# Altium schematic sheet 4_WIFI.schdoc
size 302 x 215 mm
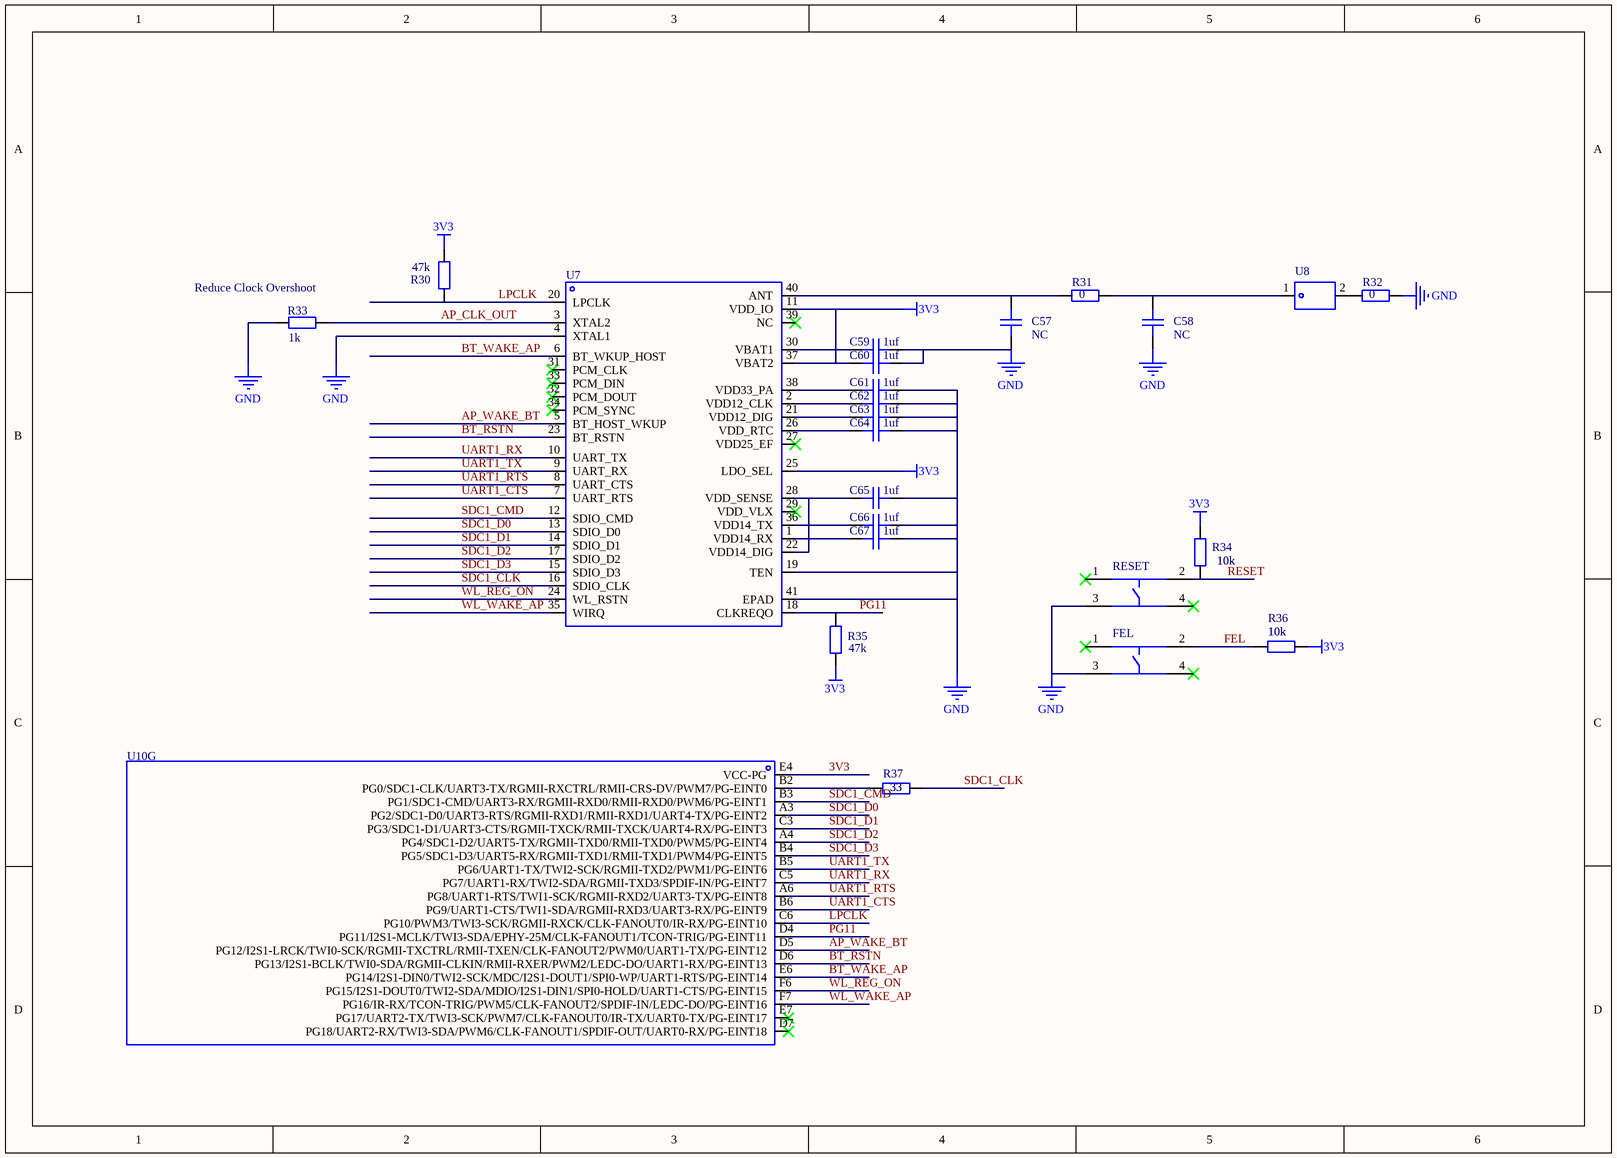
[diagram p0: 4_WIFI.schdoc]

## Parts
C57  value NC
C58  value NC
C59  value 1uf
C60  value 1uf
C61  value 1uf
C62  value 1uf
C63  value 1uf
C64  value 1uf
C65  value 1uf
C66  value 1uf
C67  value 1uf
FEL  (no value)
R30  value 47k
R31  value 0
R32  value 0
R33  value 1k
R34  10k
R35  value 47k
R36  10k
R37  33
RESET  (no value)
U7  (no value)  [QFN-40_L5.0-W5.0-P0.40-BL-EP3.4]
U8  (no value)  [FILTER-SMD_1206-2P-L3.2-W1.6-L]
U10  (no value)  [ALLWINNER D1]  (part G of 10)

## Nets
3V3: C59.1 C60.1 R30.2 R34.2 R35.2 R36.1 U7.11(VDD_IO) U7.25(LDO_SEL) U7.30(VBAT1) U7.37(VBAT2) U10.E4(VCC-PG)
GND: C57.1 C58.1 C59.2 C60.2 C61.2 C62.2 C63.2 C64.2 C65.2 C66.2 C67.2 FEL.3 R32.2 R33.2 RESET.3 U7.4(XTAL1) U7.19(TEN) U7.41(EPAD)
AP_CLK_OUT: R33.1 U7.3(XTAL2)
AP_WAKE_BT: U7.5(BT_HOST_WKUP) U10.D5(PG12/I2S1-LRCK/TWI0-SCK/RGMII-TXCTRL/RMII-TXEN/CLK-FANOUT2/PWM0/UART1-TX/PG-EINT12)
BT_RSTN: U7.23(BT_RSTN) U10.D6(PG13/I2S1-BCLK/TWI0-SDA/RGMII-CLKIN/RMII-RXER/PWM2/LEDC-DO/UART1-RX/PG-EINT13)
BT_WAKE_AP: U7.6(BT_WKUP_HOST) U10.E6(PG14/I2S1-DIN0/TWI2-SCK/MDC/I2S1-DOUT1/SPI0-WP/UART1-RTS/PG-EINT14)
FEL: FEL.2 R36.2
LPCLK: R30.1 U7.20(LPCLK) U10.C6(PG10/PWM3/TWI3-SCK/RGMII-RXCK/CLK-FANOUT0/IR-RX/PG-EINT10)
PG11: R35.1 U7.18(CLKREQO) U10.D4(PG11/I2S1-MCLK/TWI3-SDA/EPHY-25M/CLK-FANOUT1/TCON-TRIG/PG-EINT11)
RESET: R34.1 RESET.2
SDC1_CLK: R37.2 U7.16(SDIO_CLK)
SDC1_CMD: U7.12(SDIO_CMD) U10.B3(PG1/SDC1-CMD/UART3-RX/RGMII-RXD0/RMII-RXD0/PWM6/PG-EINT1)
SDC1_D0: U7.13(SDIO_D0) U10.A3(PG2/SDC1-D0/UART3-RTS/RGMII-RXD1/RMII-RXD1/UART4-TX/PG-EINT2)
SDC1_D1: U7.14(SDIO_D1) U10.C3(PG3/SDC1-D1/UART3-CTS/RGMII-TXCK/RMII-TXCK/UART4-RX/PG-EINT3)
SDC1_D2: U7.17(SDIO_D2) U10.A4(PG4/SDC1-D2/UART5-TX/RGMII-TXD0/RMII-TXD0/PWM5/PG-EINT4)
SDC1_D3: U7.15(SDIO_D3) U10.B4(PG5/SDC1-D3/UART5-RX/RGMII-TXD1/RMII-TXD1/PWM4/PG-EINT5)
UART1_CTS: U7.7(UART_RTS) U10.B6(PG9/UART1-CTS/TWI1-SDA/RGMII-RXD3/UART3-RX/PG-EINT9)
UART1_RTS: U7.8(UART_CTS) U10.A6(PG8/UART1-RTS/TWI1-SCK/RGMII-RXD2/UART3-TX/PG-EINT8)
UART1_RX: U7.10(UART_TX) U10.C5(PG7/UART1-RX/TWI2-SDA/RGMII-TXD3/SPDIF-IN/PG-EINT7)
UART1_TX: U7.9(UART_RX) U10.B5(PG6/UART1-TX/TWI2-SCK/RGMII-TXD2/PWM1/PG-EINT6)
WL_REG_ON: U7.24(WL_RSTN) U10.F6(PG15/I2S1-DOUT0/TWI2-SDA/MDIO/I2S1-DIN1/SPI0-HOLD/UART1-CTS/PG-EINT15)
WL_WAKE_AP: U7.35(WIRQ) U10.F7(PG16/IR-RX/TCON-TRIG/PWM5/CLK-FANOUT2/SPDIF-IN/LEDC-DO/PG-EINT16)
NetC57_2: C57.2 R31.1 U7.40(ANT)
NetC58_2: C58.2 R31.2 U8.1
NetC61_1: C61.1 U7.38(VDD33_PA)
NetC62_1: C62.1 U7.2(VDD12_CLK)
NetC63_1: C63.1 U7.21(VDD12_DIG)
NetC64_1: C64.1 U7.26(VDD_RTC)
NetC65_1: C65.1 C66.1 C67.1 U7.1(VDD14_RX) U7.22(VDD14_DIG) U7.28(VDD_SENSE) U7.36(VDD14_TX)
NetR32_1: R32.1 U8.2
NetR37_1: R37.1 U10.B2(PG0/SDC1-CLK/UART3-TX/RGMII-RXCTRL/RMII-CRS-DV/PWM7/PG-EINT0)

Not connected (* = marked no-connect by the designer): FEL 1* 4*; RESET 1* 4*; U7 27(VDD25_EF)* 29(VDD_VLX)* 31(PCM_CLK)* 32(PCM_DOUT)* 33(PCM_DIN)* 34(PCM_SYNC)* 39(NC)*; U10 D7(PG18/UART2-RX/TWI3-SDA/PWM6/CLK-FANOUT1/SPDIF-OUT/UART0-RX/PG-EINT18)* E7(PG17/UART2-TX/TWI3-SCK/PWM7/CLK-FANOUT0/IR-TX/UART0-TX/PG-EINT17)*

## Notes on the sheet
- (near R33) Reduce Clock Overshoot

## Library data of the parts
C57-C67 = FN15X104K250PNG: Manufacturer: PSA(信昌电陶); Add into BOM: yes; Tolerance: ±10%; Voltage Rated: 25V; Temperature Coefficient: X7R; Description: 容值:100nF;精度:±10%;额定电压:25V;温度系数:X7R;; NAME: 1; Pin Type: IN
FEL RESET = PTS810SJM250SMTRLFS: Manufacturer: C&K; Add into BOM: yes; Contact Current: 50mA; Voltage Rating (DC): 16V; Circuit: 单刀单掷; Actuator Style: 圆形按钮; Switch Length: 4.2mm; Switch Width: 3.2mm; Switch Height: 2.5mm; Description: 触点电流:50mA;额定电压(DC):16V;电路结构:单刀单掷;安装方式:立贴;按钮形状:圆形按钮;带灯:-;开关长度:4.2mm;开关宽度:3.2mm;开关高度:2.5mm;; NAME: 4; Pin Type: IN
R30-R33 R35 = TR0402D10K0Q1025Z: Manufacturer: EVER OHMS(天二科技); Symbol: TR0402D10KQ1025; Add into BOM: yes; Tolerance: ±0.5%; Power(Watts): 63mW; Temperature Coefficient: ±25ppm/; Overload Voltage (Max): 25V; Description: 电阻类型:薄膜电阻;阻值:10k;精度:±0.5%;功率:63mW;温度系数:±25ppm/;最大工作电压:25V;工作温度范围:-55~+155;; NAME: 1; Pin Type: IN
R34 R36 = R0402_2: Symbol: R0402_1; Convert to PCB: yes; NAME: 1; Pin Type: IN
R37 = R0402_1: Symbol: R0402; Convert to PCB: yes; NAME: 1; Pin Type: IN
U7 = XR829: Manufacturer: Allwinner; Add into BOM: yes
U8 = RFANT3216120A5T: Manufacturer: 华新科(Walsin); Add into BOM: yes; Description: 射频系列/标准:-;频率（中心/带）:-;频带数:-;电压驻波比（最大值）:-;回波损耗（最小值）:-;增益:-;; NAME: 2; Pin Type: IN
U10 = Allwinner D1-H: Pin Type: IN; Add into BOM: yes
